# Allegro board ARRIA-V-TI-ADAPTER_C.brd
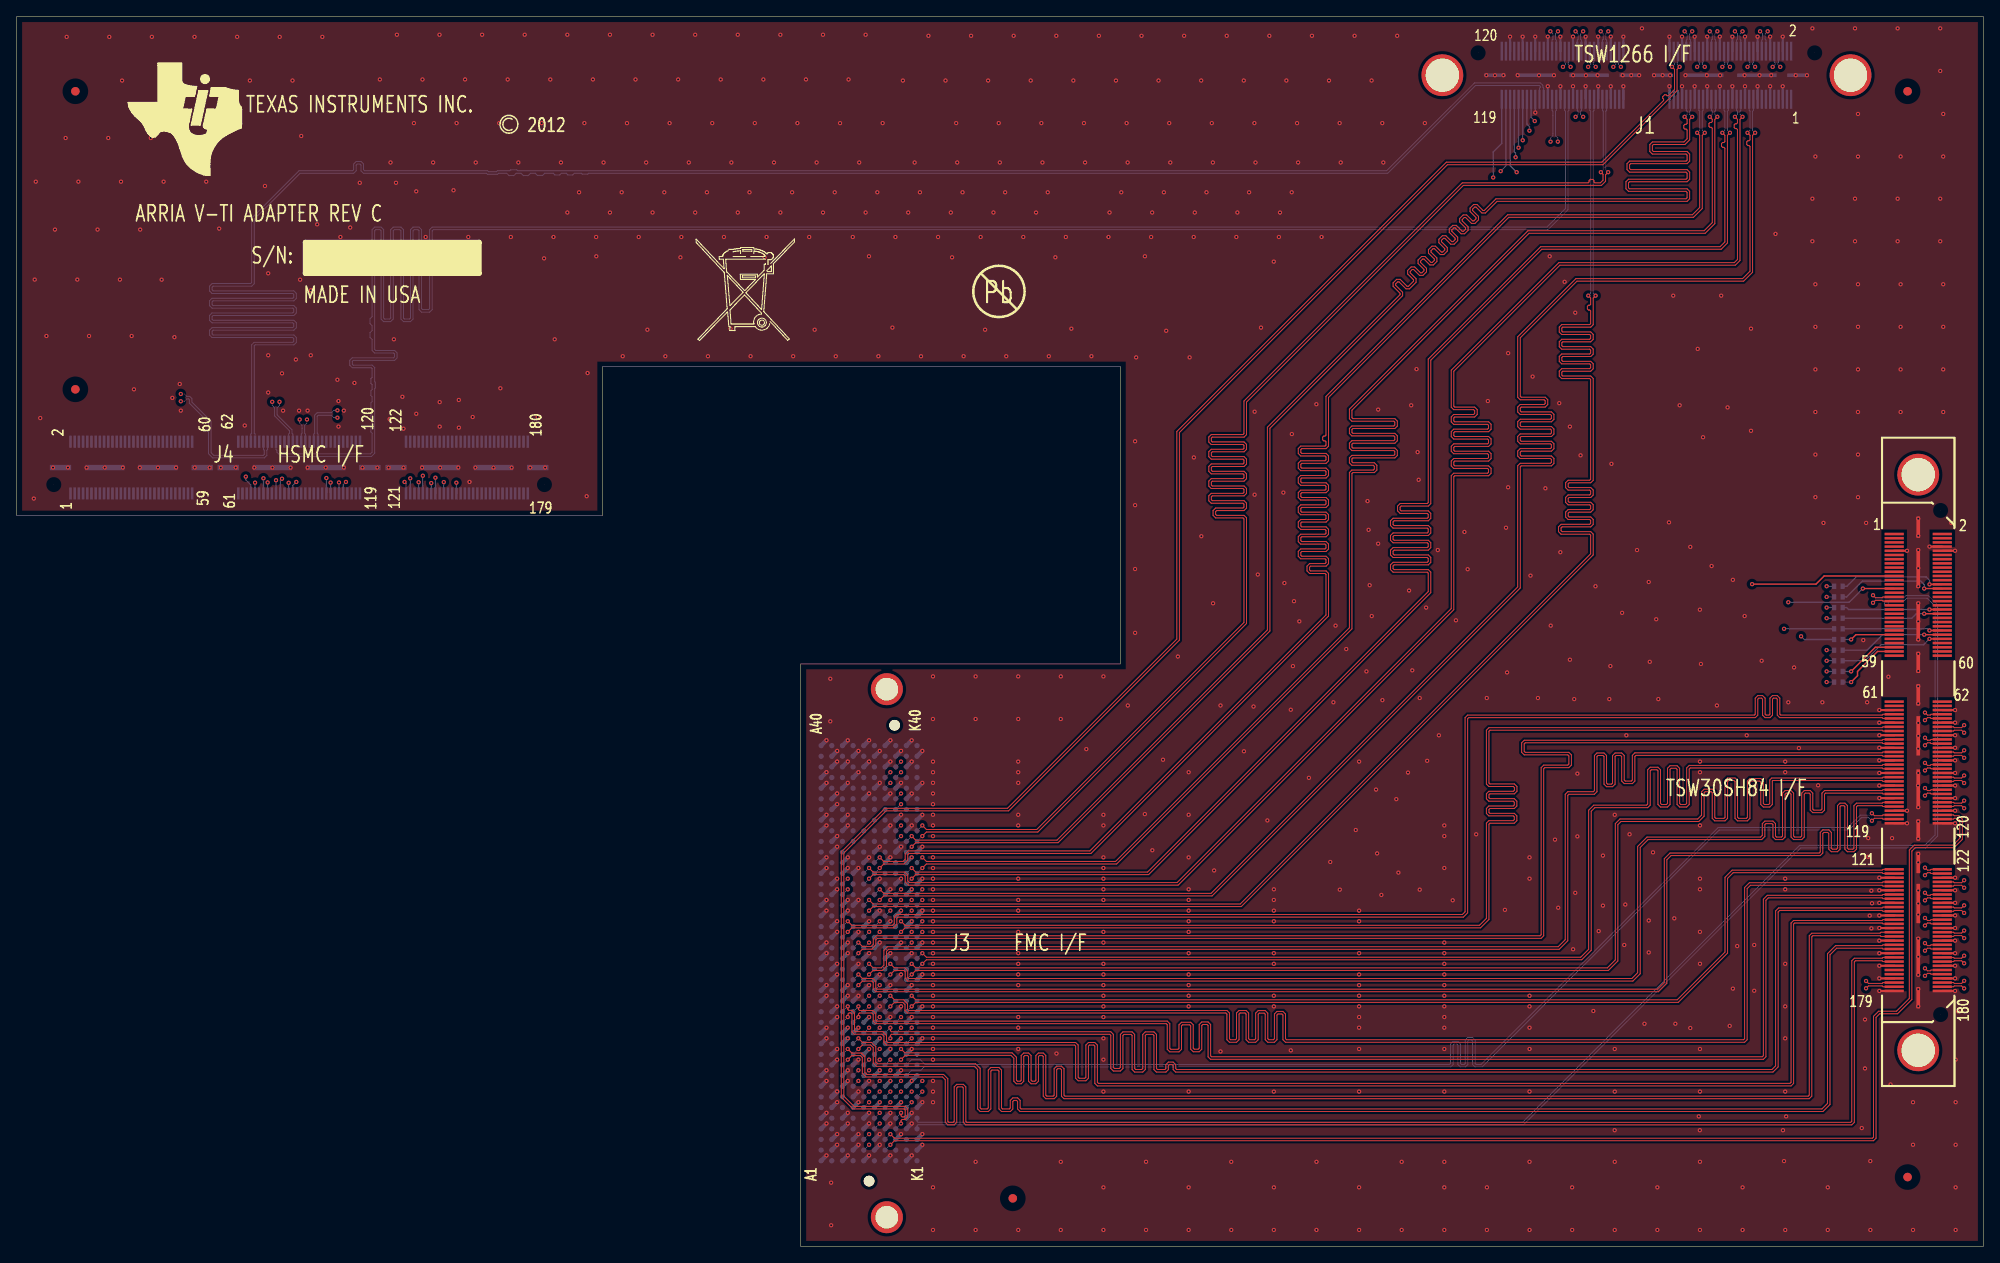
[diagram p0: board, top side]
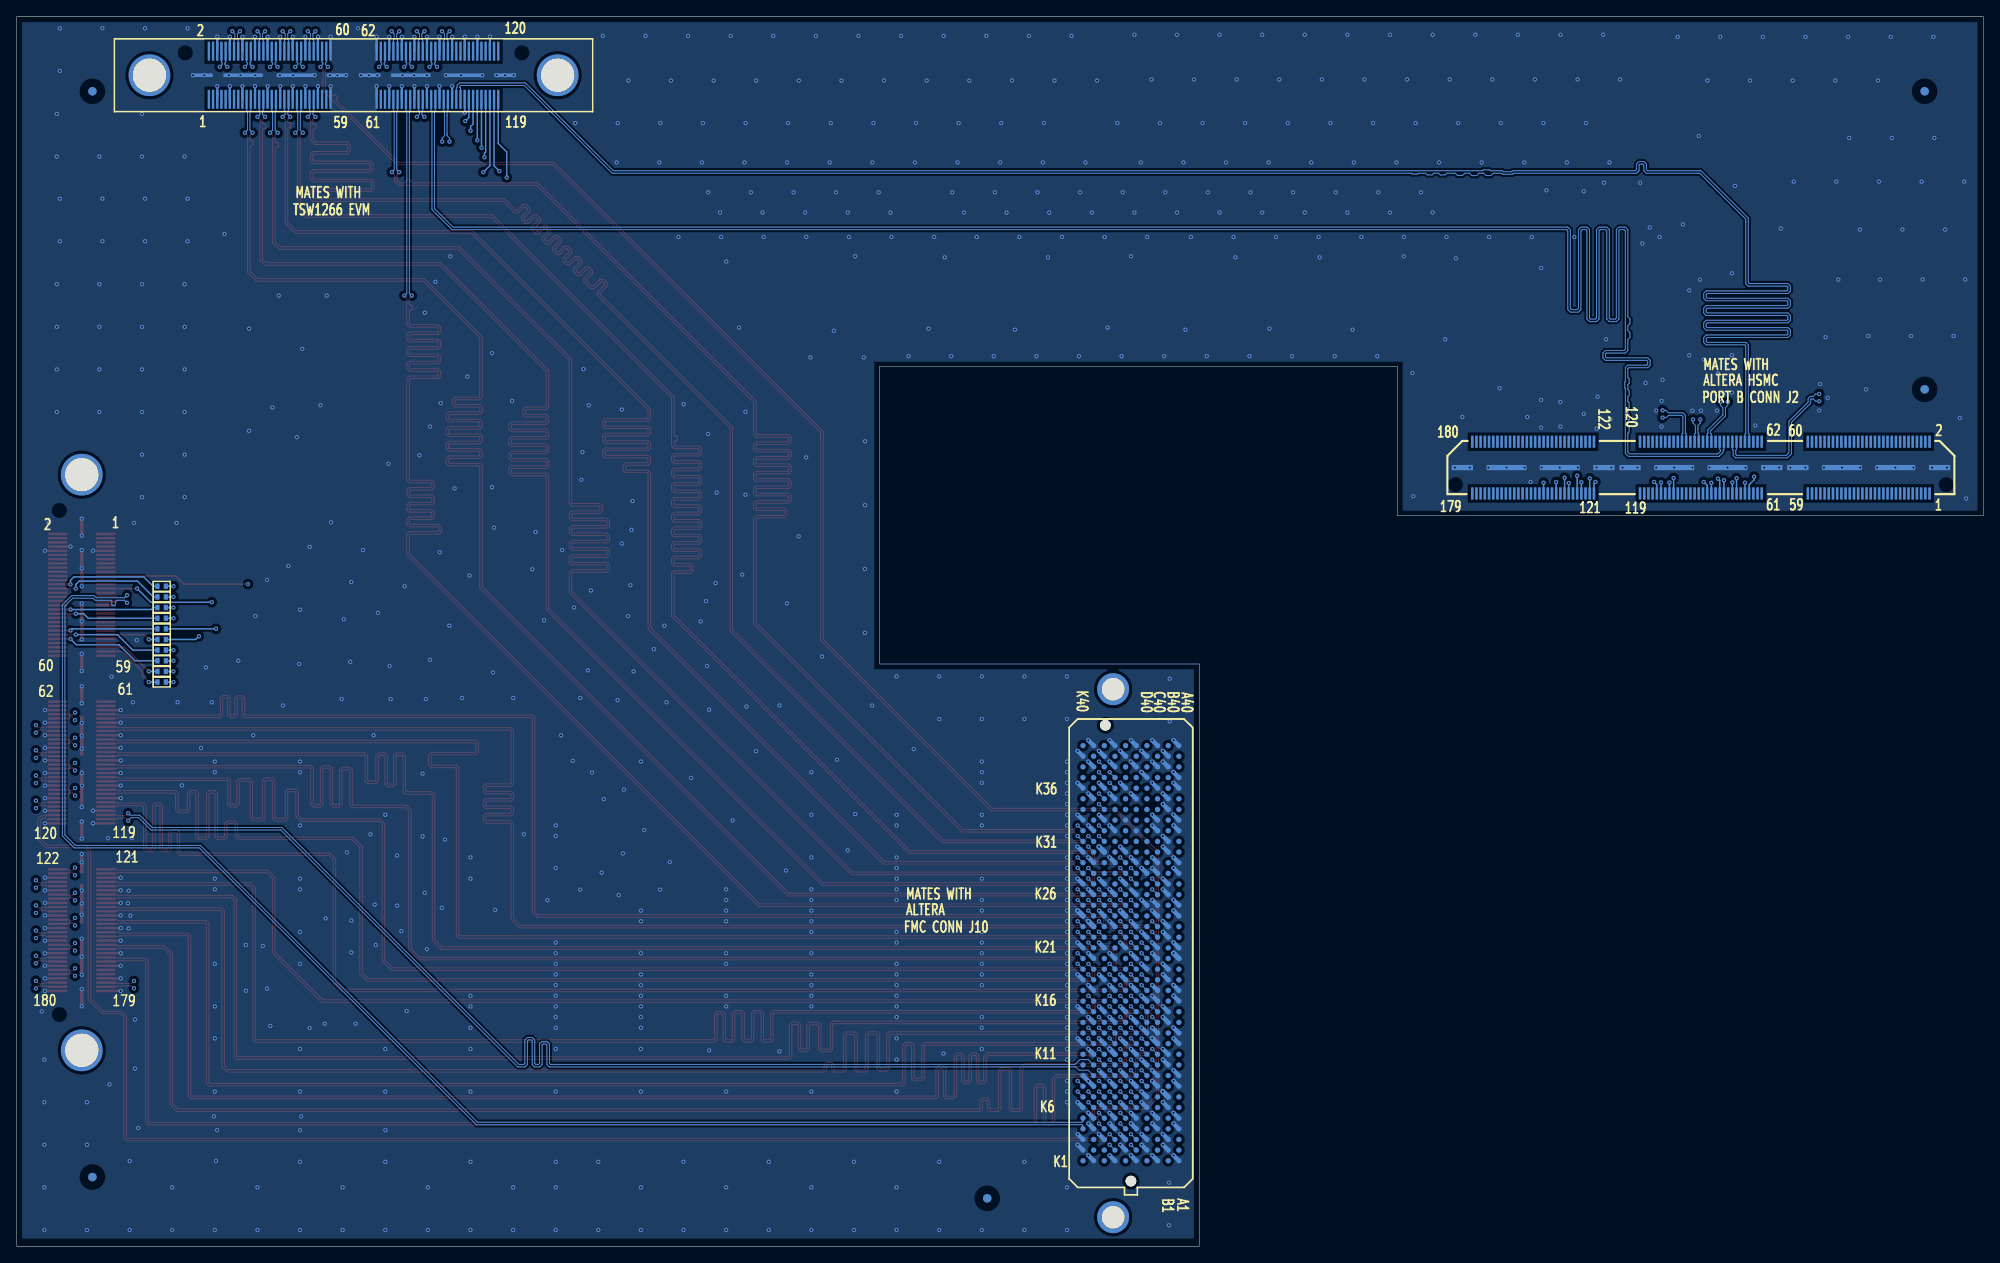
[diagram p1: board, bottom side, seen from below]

Outline 234.44 x 146.69 mm; copper layers: TOP, LAYER2_GND1, LAYER3, LAYER4_GND2, LAYER5_GND3, LAYER6, LAYER7_GND4, BOTTOM. Coordinates in mm from the lower left corner of the outline.
Outline path: 0,146.69 0,87.17 69.85,87.17 69.85,104.95 131.57,104.95 131.57,69.47 93.47,69.47 93.47,0 234.44,0 234.44,146.69 0,146.69

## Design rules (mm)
net group CDA0: nets DA0N DA0P
net group CDA10: nets DA10N DA10P
net group CDA11: nets DA11N DA11P
net group DDA1: nets DA1N DA1P
net group DDA2: nets DA2N DA2P
net group DDA3: nets DA3N DA3P
net group DDA4: nets DA4N DA4P
net group DDA5: nets DA5N DA5P
net group DDA6: nets DA6N DA6P
net group DDA7: nets DA7N DA7P
net group DDA8: nets DA8N DA8P
net group DDA9: nets DA9N DA9P
net group DDA12: nets DA12N DA12P
net group DDA13: nets DA13N DA13P
net group DDA14: nets DA14N DA14P
net group DDA15: nets DA15N DA15P
net group DDATACLK: nets DATACLKN DATACLKP
net group DDB0: nets DB0N DB0P
net group DDB1: nets DB1N DB1P
net group DDB2: nets DB2N DB2P
net group DDB3: nets DB3N DB3P
net group DDB4: nets DB4N DB4P
net group DDB5: nets DB5N DB5P
net group DDB6: nets DB6N DB6P
net group DDB7: nets DB7N DB7P
net group DDB8: nets DB8N DB8P
net group DDB9: nets DB9N DB9P
net group DDB10: nets DB10N DB10P
net group DDB11: nets DB11N DB11P
net group DDB12: nets DB12N DB12P
net group DDB13: nets DB13N DB13P
net group DDB14: nets DB14N DB14P
net group DDB15: nets DB15N DB15P
net group DIFFPAIR0: nets ADC_A0N ADC_A0P
net group DIFFPAIR1: nets ADC_A10N ADC_A10P
net group DIFFPAIR2: nets ADC_A11N ADC_A11P
net group DIFFPAIR3: nets ADC_A1N ADC_A1P
net group DIFFPAIR4: nets ADC_A2N ADC_A2P
net group DIFFPAIR5: nets ADC_A3N ADC_A3P
net group DIFFPAIR6: nets ADC_A4N ADC_A4P
net group DIFFPAIR7: nets ADC_A5N ADC_A5P
net group DIFFPAIR8: nets ADC_A6N ADC_A6P
net group DIFFPAIR9: nets ADC_A7N ADC_A7P
net group DIFFPAIR10: nets ADC_A8N ADC_A8P
net group DIFFPAIR11: nets ADC_A9N ADC_A9P
net group DIFFPAIR12: nets ADC_B0N ADC_B0P
net group DIFFPAIR13: nets ADC_B10N ADC_B10P
net group DIFFPAIR14: nets ADC_B11N ADC_B11P
net group DIFFPAIR15: nets ADC_B1N ADC_B1P
net group DIFFPAIR16: nets ADC_B2N ADC_B2P
net group DIFFPAIR17: nets ADC_B4N ADC_B4P
net group DIFFPAIR18: nets ADC_B3N ADC_B3P
net group DIFFPAIR19: nets ADC_B5N ADC_B5P
net group DIFFPAIR20: nets ADC_B6N ADC_B6P
net group DIFFPAIR21: nets ADC_B7N ADC_B7P
net group DIFFPAIR22: nets ADC_B8N ADC_B8P
net group DIFFPAIR23: nets FPGA_CLKOUTN2 FPGA_CLKOUTP2
net group DIFFPAIR24: nets FPGA_CLKOUTN1 FPGA_CLKOUTP1
net group DIFFPAIR25: nets ADC_B9N ADC_B9P
net group DIFFPAIR26: nets CLKOUTAN CLKOUTAP
net group DIFFPAIR27: nets ISTROBE_N ISTROBE_P
net group DIFFPAIR28: nets PARITY_N PARITY_P
net group DIFFPAIR29: nets SYNCA_N SYNCA_P
net group DIFFPAIR30: nets OVR_AN OVR_AP
net group OVRB: nets OVR_BN OVR_BP

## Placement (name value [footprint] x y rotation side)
J1  CON, SMVT, 120POS, HS GND PLANE, QSH  [CON_SMVT_120POS_QSH_SAMTEC_RT1]  194.29 139.71 180 bottom
J2  CON, SMVT, 180POS, HS GND PLANE, QSH  [CON_SMVT_180POS_QSH_SAMTEC_RT1]  229.36 87.82 270 top
J3  CON, SMVT, 40X10, ASP  [CON_SMVT_40X10_ASP-134487-01]  101.61 34.96 270 bottom
J4  CON, SMVT, 180POS, HS GND PLANE, ASP-QTH  [CON_SMVT_180POS_QTH_SAMTEC]  33.66 92.9 0 bottom
NOREF  -  []  93.47 0 90 top
NOREF#2  -  []  0 87.17 90 top
NOREF#3  -  []  180.72 171.45 0 top
NOREF#4  -  []  -124.46 -158.75 0 top
NOREF#5  -  []  0 146.69 0 top
NOREF#6  -  []  255.4 178.94 0 top
NOREF#7  -  []  131.57 69.47 90 top
NOREF#8  -  []  668.02 176.78 0 top
NOREF#9  -  []  234.44 0 90 top
NOREF#10  -  [unnamed#2]  225.43 137.79 0 top
NOREF#11  -  []  124.97 200.28 0 top
NOREF#12  -  []  209.55 48.26 0 top
NOREF#13  -  []  268.61 177.29 0 top
NOREF#14  -  []  -110.49 320.68 0 top
NOREF#15  -  []  93.47 0 0 top
NOREF#16  -  []  57.68 143.92 0 top
NOREF#17  -  []  223.29 96.44 0 top
NOREF#18  -  []  0 87.17 90 top
NOREF#19  -  []  189.94 170.1 0 top
NOREF#20  -  []  240.31 178.44 0 top
NOREF#21  -  [unnamed#2]  6.98 137.79 0 top
NOREF#22  -  []  93.47 0 0 top
NOREF#23  -  [unnamed#2]  6.98 102.23 0 top
NOREF#24  -  []  69.85 104.95 0 top
NOREF#25  -  [unnamed#2]  118.74 5.71 0 top
NOREF#26  -  []  93.47 31.59 0 top
NOREF#27  -  []  13.68 88.69 0 top
NOREF#28  -  [unnamed#2]  225.43 8.26 0 top
NOREF#29  -  []  93.47 0 90 top
NOREF#30  -  [unnamed#2]  225.43 8.26 180 bottom
NOREF#31  -  [unnamed#2]  6.98 137.79 180 bottom
NOREF#32  -  [unnamed#2]  103.73 3.46 180 bottom
NOREF#33  -  [unnamed#2]  6.98 102.23 180 bottom
NOREF#34  -  [unnamed#2]  225.43 137.79 180 bottom
NOREF#35  -  [unnamed#2]  103.73 66.46 180 bottom
NOREF#36  -  [unnamed#2]  118.74 5.71 180 bottom
R1  0  [0402]  217.17 78.74 0 bottom
R2  0  [0402]  217.17 77.47 0 bottom
R3  0  [0402]  217.17 76.2 0 bottom
R4  0  [0402]  217.17 74.93 0 bottom
R5  0  [0402]  217.17 73.66 0 bottom
R7  0  [0402]  217.17 71.12 0 bottom
R8  0  [0402]  217.17 72.39 180 bottom
R9  0  [0402]  217.17 69.85 0 bottom
R12  0  [0402]  217.17 68.58 180 bottom
R14  0  [0402]  217.17 67.31 180 bottom

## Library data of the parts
J1 = CON_SMVT_120POS_QSH_SAMTEC
J2 = CON_SMVT_180POS_QSH_SAMTEC
J3 = CON_SMVT_40X10_ASP-134487-01
J4 = CON_SMVT_180POS_QTH_SAMTEC
R1-R5 R7-R9 R12 R14 = R_5

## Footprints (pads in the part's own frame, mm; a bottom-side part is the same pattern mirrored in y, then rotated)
0402
  rect 0.508x0.635 smd: 1(-0.508,0) 2(0.508,0)
CON_SMVT_40X10_ASP-134487-01
  round 1.27 hole 1.27 unplated: (-27.191,-3.048) (27.191,0)
  round 0.635 smd: A1(24.765,5.715) A2(23.495,5.715) A3(22.225,5.715) A4(20.955,5.715) A5(19.685,5.715) A6(18.415,5.715) A7(17.145,5.715) A8(15.875,5.715) A9(14.605,5.715) A10(13.335,5.715) A11(12.065,5.715) A12(10.795,5.715) A13(9.525,5.715) A14(8.255,5.715) A15(6.985,5.715) A16(5.715,5.715) A17(4.445,5.715) A18(3.175,5.715) A19(1.905,5.715) A20(0.635,5.715) A21(-0.635,5.715) A22(-1.905,5.715) A23(-3.175,5.715) A24(-4.445,5.715) A25(-5.715,5.715) A26(-6.985,5.715) A27(-8.255,5.715) A28(-9.525,5.715) A29(-10.795,5.715) A30(-12.065,5.715) A31(-13.335,5.715) A32(-14.605,5.715) A33(-15.875,5.715) A34(-17.145,5.715) A35(-18.415,5.715) A36(-19.685,5.715) A37(-20.955,5.715) A38(-22.225,5.715) A39(-23.495,5.715) A40(-24.765,5.715) B1(24.765,4.445) B2(23.495,4.445) B3(22.225,4.445) B4(20.955,4.445) B5(19.685,4.445) B6(18.415,4.445) B7(17.145,4.445) B8(15.875,4.445) B9(14.605,4.445) B10(13.335,4.445) B11(12.065,4.445) B12(10.795,4.445) B13(9.525,4.445) B14(8.255,4.445) B15(6.985,4.445) B16(5.715,4.445) B17(4.445,4.445) B18(3.175,4.445) B19(1.905,4.445) B20(0.635,4.445) B21(-0.635,4.445) B22(-1.905,4.445) B23(-3.175,4.445) B24(-4.445,4.445) B25(-5.715,4.445) B26(-6.985,4.445) B27(-8.255,4.445) B28(-9.525,4.445) B29(-10.795,4.445) B30(-12.065,4.445) B31(-13.335,4.445) B32(-14.605,4.445) B33(-15.875,4.445) B34(-17.145,4.445) B35(-18.415,4.445) B36(-19.685,4.445) B37(-20.955,4.445) B38(-22.225,4.445) B39(-23.495,4.445) B40(-24.765,4.445) C1(24.765,3.175) C2(23.495,3.175) C3(22.225,3.175) C4(20.955,3.175) C5(19.685,3.175) C6(18.415,3.175) C7(17.145,3.175) C8(15.875,3.175) C9(14.605,3.175) C10(13.335,3.175) C11(12.065,3.175) C12(10.795,3.175) C13(9.525,3.175) C14(8.255,3.175) C15(6.985,3.175) C16(5.715,3.175) C17(4.445,3.175) C18(3.175,3.175) C19(1.905,3.175) C20(0.635,3.175) C21(-0.635,3.175) C22(-1.905,3.175) C23(-3.175,3.175) C24(-4.445,3.175) C25(-5.715,3.175) C26(-6.985,3.175) C27(-8.255,3.175) C28(-9.525,3.175) C29(-10.795,3.175) C30(-12.065,3.175) C31(-13.335,3.175) C32(-14.605,3.175) C33(-15.875,3.175) C34(-17.145,3.175) C35(-18.415,3.175) C36(-19.685,3.175) C37(-20.955,3.175) C38(-22.225,3.175) C39(-23.495,3.175) C40(-24.765,3.175) D1(24.765,1.905) D2(23.495,1.905) D3(22.225,1.905) D4(20.955,1.905) D5(19.685,1.905) D6(18.415,1.905) D7(17.145,1.905) D8(15.875,1.905) D9(14.605,1.905) D10(13.335,1.905) D11(12.065,1.905) D12(10.795,1.905) D13(9.525,1.905) D14(8.255,1.905) D15(6.985,1.905) D16(5.715,1.905) D17(4.445,1.905) D18(3.175,1.905) D19(1.905,1.905) D20(0.635,1.905) D21(-0.635,1.905) D22(-1.905,1.905) D23(-3.175,1.905) D24(-4.445,1.905) D25(-5.715,1.905) D26(-6.985,1.905) D27(-8.255,1.905) D28(-9.525,1.905) D29(-10.795,1.905) D30(-12.065,1.905) D31(-13.335,1.905) D32(-14.605,1.905) D33(-15.875,1.905) D34(-17.145,1.905) D35(-18.415,1.905) D36(-19.685,1.905) D37(-20.955,1.905) D38(-22.225,1.905) D39(-23.495,1.905) D40(-24.765,1.905) E1(24.765,0.635) E2(23.495,0.635) E3(22.225,0.635) E4(20.955,0.635) E5(19.685,0.635) E6(18.415,0.635) E7(17.145,0.635) E8(15.875,0.635) E9(14.605,0.635) E10(13.335,0.635) E11(12.065,0.635) E12(10.795,0.635) E13(9.525,0.635) E14(8.255,0.635) E15(6.985,0.635) E16(5.715,0.635) E17(4.445,0.635) E18(3.175,0.635) E19(1.905,0.635) E20(0.635,0.635) E21(-0.635,0.635) E22(-1.905,0.635) E23(-3.175,0.635) E24(-4.445,0.635) E25(-5.715,0.635) E26(-6.985,0.635) E27(-8.255,0.635) E28(-9.525,0.635) E29(-10.795,0.635) E30(-12.065,0.635) E31(-13.335,0.635) E32(-14.605,0.635) E33(-15.875,0.635) E34(-17.145,0.635) E35(-18.415,0.635) E36(-19.685,0.635) E37(-20.955,0.635) E38(-22.225,0.635) E39(-23.495,0.635) E40(-24.765,0.635) F1(24.765,-0.635) F2(23.495,-0.635) F3(22.225,-0.635) F4(20.955,-0.635) F5(19.685,-0.635) F6(18.415,-0.635) F7(17.145,-0.635) F8(15.875,-0.635) F9(14.605,-0.635) F10(13.335,-0.635) F11(12.065,-0.635) F12(10.795,-0.635) F13(9.525,-0.635) F14(8.255,-0.635) F15(6.985,-0.635) F16(5.715,-0.635) F17(4.445,-0.635) F18(3.175,-0.635) F19(1.905,-0.635) F20(0.635,-0.635) F21(-0.635,-0.635) F22(-1.905,-0.635) F23(-3.175,-0.635) F24(-4.445,-0.635) F25(-5.715,-0.635) F26(-6.985,-0.635) F27(-8.255,-0.635) F28(-9.525,-0.635) F29(-10.795,-0.635) F30(-12.065,-0.635) F31(-13.335,-0.635) F32(-14.605,-0.635) F33(-15.875,-0.635) F34(-17.145,-0.635) F35(-18.415,-0.635) F36(-19.685,-0.635) F37(-20.955,-0.635) F38(-22.225,-0.635) F39(-23.495,-0.635) F40(-24.765,-0.635) G1(24.765,-1.905) G2(23.495,-1.905) G3(22.225,-1.905) G4(20.955,-1.905) G5(19.685,-1.905) G6(18.415,-1.905) G7(17.145,-1.905) G8(15.875,-1.905) G9(14.605,-1.905) G10(13.335,-1.905) G11(12.065,-1.905) G12(10.795,-1.905) G13(9.525,-1.905) G14(8.255,-1.905) G15(6.985,-1.905) G16(5.715,-1.905) G17(4.445,-1.905) G18(3.175,-1.905) G19(1.905,-1.905) G20(0.635,-1.905) G21(-0.635,-1.905) G22(-1.905,-1.905) G23(-3.175,-1.905) G24(-4.445,-1.905) G25(-5.715,-1.905) G26(-6.985,-1.905) G27(-8.255,-1.905) G28(-9.525,-1.905) G29(-10.795,-1.905) G30(-12.065,-1.905) G31(-13.335,-1.905) G32(-14.605,-1.905) G33(-15.875,-1.905) G34(-17.145,-1.905) G35(-18.415,-1.905) G36(-19.685,-1.905) G37(-20.955,-1.905) G38(-22.225,-1.905) G39(-23.495,-1.905) G40(-24.765,-1.905) H1(24.765,-3.175) H2(23.495,-3.175) H3(22.225,-3.175) H4(20.955,-3.175) H5(19.685,-3.175) H6(18.415,-3.175) H7(17.145,-3.175) H8(15.875,-3.175) H9(14.605,-3.175) H10(13.335,-3.175) H11(12.065,-3.175) H12(10.795,-3.175) H13(9.525,-3.175) H14(8.255,-3.175) H15(6.985,-3.175) H16(5.715,-3.175) H17(4.445,-3.175) H18(3.175,-3.175) H19(1.905,-3.175) H20(0.635,-3.175) H21(-0.635,-3.175) H22(-1.905,-3.175) H23(-3.175,-3.175) H24(-4.445,-3.175) H25(-5.715,-3.175) H26(-6.985,-3.175) H27(-8.255,-3.175) H28(-9.525,-3.175) H29(-10.795,-3.175) H30(-12.065,-3.175) H31(-13.335,-3.175) H32(-14.605,-3.175) H33(-15.875,-3.175) H34(-17.145,-3.175) H35(-18.415,-3.175) H36(-19.685,-3.175) H37(-20.955,-3.175) H38(-22.225,-3.175) H39(-23.495,-3.175) H40(-24.765,-3.175) J1(24.765,-4.445) J2(23.495,-4.445) J3(22.225,-4.445) J4(20.955,-4.445) J5(19.685,-4.445) J6(18.415,-4.445) J7(17.145,-4.445) J8(15.875,-4.445) J9(14.605,-4.445) J10(13.335,-4.445) J11(12.065,-4.445) J12(10.795,-4.445) J13(9.525,-4.445) J14(8.255,-4.445) J15(6.985,-4.445) J16(5.715,-4.445) J17(4.445,-4.445) J18(3.175,-4.445) J19(1.905,-4.445) J20(0.635,-4.445) J21(-0.635,-4.445) J22(-1.905,-4.445) J23(-3.175,-4.445) J24(-4.445,-4.445) J25(-5.715,-4.445) J26(-6.985,-4.445) J27(-8.255,-4.445) J28(-9.525,-4.445) J29(-10.795,-4.445) J30(-12.065,-4.445) J31(-13.335,-4.445) J32(-14.605,-4.445) J33(-15.875,-4.445) J34(-17.145,-4.445) J35(-18.415,-4.445) J36(-19.685,-4.445) J37(-20.955,-4.445) J38(-22.225,-4.445) J39(-23.495,-4.445) J40(-24.765,-4.445) K1(24.765,-5.715) K2(23.495,-5.715) K3(22.225,-5.715) K4(20.955,-5.715) K5(19.685,-5.715) K6(18.415,-5.715) K7(17.145,-5.715) K8(15.875,-5.715) K9(14.605,-5.715) K10(13.335,-5.715) K11(12.065,-5.715) K12(10.795,-5.715) K13(9.525,-5.715) K14(8.255,-5.715) K15(6.985,-5.715) K16(5.715,-5.715) K17(4.445,-5.715) K18(3.175,-5.715) K19(1.905,-5.715) K20(0.635,-5.715) K21(-0.635,-5.715) K22(-1.905,-5.715) K23(-3.175,-5.715) K24(-4.445,-5.715) K25(-5.715,-5.715) K26(-6.985,-5.715) K27(-8.255,-5.715) K28(-9.525,-5.715) K29(-10.795,-5.715) K30(-12.065,-5.715) K31(-13.335,-5.715) K32(-14.605,-5.715) K33(-15.875,-5.715) K34(-17.145,-5.715) K35(-18.415,-5.715) K36(-19.685,-5.715) K37(-20.955,-5.715) K38(-22.225,-5.715) K39(-23.495,-5.715) K40(-24.765,-5.715)
CON_SMVT_120POS_QSH_SAMTEC_RT1
  round 4.978 hole 3.962: (-24.332,0) (24.332,0)
  round 0.025 hole 1.016 unplated: (-20.06,2.67) (20.07,2.67)
  rect 0.279x2.261 smd: 1(-17.25,-2.87) 2(-17.25,2.87) 3(-16.75,-2.87) 4(-16.75,2.87) 5(-16.25,-2.87) 6(-16.25,2.87) 7(-15.75,-2.87) 8(-15.75,2.87) 9(-15.25,-2.87) 10(-15.25,2.87) 11(-14.75,-2.87) 12(-14.75,2.87) 13(-14.25,-2.87) 14(-14.25,2.87) 15(-13.75,-2.87) 16(-13.75,2.87) 17(-13.25,-2.87) 18(-13.25,2.87) 19(-12.75,-2.87) 20(-12.75,2.87) 21(-12.25,-2.87) 22(-12.25,2.87) 23(-11.75,-2.87) 24(-11.75,2.87) 25(-11.25,-2.87) 26(-11.25,2.87) 27(-10.75,-2.87) 28(-10.75,2.87) 29(-10.25,-2.87) 30(-10.25,2.87) 31(-9.75,-2.87) 32(-9.75,2.87) 33(-9.25,-2.87) 34(-9.25,2.87) 35(-8.75,-2.87) 36(-8.75,2.87) 37(-8.25,-2.87) 38(-8.25,2.87) 39(-7.75,-2.87) 40(-7.75,2.87) 41(-7.25,-2.87) 42(-7.25,2.87) 43(-6.75,-2.87) 44(-6.75,2.87) 45(-6.25,-2.87) 46(-6.25,2.87) 47(-5.75,-2.87) 48(-5.75,2.87) 49(-5.25,-2.87) 50(-5.25,2.87) 51(-4.75,-2.87) 52(-4.75,2.87) 53(-4.25,-2.87) 54(-4.25,2.87) 55(-3.75,-2.87) 56(-3.75,2.87) 57(-3.25,-2.87) 58(-3.25,2.87) 59(-2.75,-2.87) 60(-2.75,2.87) 61(2.75,-2.87) 62(2.75,2.87) 63(3.25,-2.87) 64(3.25,2.87) 65(3.75,-2.87) 66(3.75,2.87) 67(4.25,-2.87) 68(4.25,2.87) 69(4.75,-2.87) 70(4.75,2.87) 71(5.25,-2.87) 72(5.25,2.87) 73(5.75,-2.87) 74(5.75,2.87) 75(6.25,-2.87) 76(6.25,2.87) 77(6.75,-2.87) 78(6.75,2.87) 79(7.25,-2.87) 80(7.25,2.87) 81(7.75,-2.87) 82(7.75,2.87) 83(8.25,-2.87) 84(8.25,2.87) 85(8.75,-2.87) 86(8.75,2.87) 87(9.25,-2.87) 88(9.25,2.87) 89(9.75,-2.87) 90(9.75,2.87) 91(10.25,-2.87) 92(10.25,2.87) 93(10.75,-2.87) 94(10.75,2.87) 95(11.25,-2.87) 96(11.25,2.87) 97(11.75,-2.87) 98(11.75,2.87) 99(12.25,-2.87) 100(12.25,2.87) 101(12.75,-2.87) 102(12.75,2.87) 103(13.25,-2.87) 104(13.25,2.87) 105(13.75,-2.87) 106(13.75,2.87) 107(14.25,-2.87) 108(14.25,2.87) 109(14.75,-2.87) 110(14.75,2.87) 111(15.25,-2.87) 112(15.25,2.87) 113(15.75,-2.87) 114(15.75,2.87) 115(16.25,-2.87) 116(16.25,2.87) 117(16.75,-2.87) 118(16.75,2.87) 119(17.25,-2.87) 120(17.25,2.87)
  rect 2.54x0.432 smd: 121(-18.06,0) 124(-1.93,0) 125(1.94,0) 128(18.07,0)
  rect 4.699x0.432 smd: 122(-13.17,0) 123(-6.82,0) 126(6.83,0) 127(13.18,0)
CON_SMVT_180POS_QSH_SAMTEC_RT1
  round 4.978 hole 3.962: (-4.234,-2.667) (64.447,-2.667)
  round 0.025 hole 1.016 unplated: (0.036,0) (60.175,0)
  rect 0.305x2.286 smd: 1(2.847,-5.532) 2(2.847,0.198) 3(3.348,-5.532) 4(3.348,0.198) 5(3.848,-5.532) 6(3.848,0.198) 7(4.348,-5.532) 8(4.348,0.198) 9(4.849,-5.532) 10(4.849,0.198) 11(5.349,-5.532) 12(5.349,0.198) 13(5.85,-5.532) 14(5.85,0.198) 15(6.35,-5.532) 16(6.35,0.198) 17(6.85,-5.532) 18(6.85,0.198) 19(7.351,-5.532) 20(7.351,0.198) 21(7.851,-5.532) 22(7.851,0.198) 23(8.352,-5.532) 24(8.352,0.198) 25(8.852,-5.532) 26(8.852,0.198) 27(9.352,-5.532) 28(9.352,0.198) 29(9.853,-5.532) 30(9.853,0.198) 31(10.353,-5.532) 32(10.353,0.198) 33(10.853,-5.532) 34(10.853,0.198) 35(11.354,-5.532) 36(11.354,0.198) 37(11.854,-5.532) 38(11.854,0.198) 39(12.355,-5.532) 40(12.355,0.198) 41(12.855,-5.532) 42(12.855,0.198) 43(13.355,-5.532) 44(13.355,0.198) 45(13.856,-5.532) 46(13.856,0.198) 47(14.356,-5.532) 48(14.356,0.198) 49(14.856,-5.532) 50(14.856,0.198) 51(15.357,-5.532) 52(15.357,0.198) 53(15.857,-5.532) 54(15.857,0.198) 55(16.358,-5.532) 56(16.358,0.198) 57(16.858,-5.532) 58(16.858,0.198) 59(17.358,-5.532) 60(17.358,0.198) 61(22.85,-5.532) 62(22.85,0.198) 63(23.35,-5.532) 64(23.35,0.198) 65(23.851,-5.532) 66(23.851,0.198) 67(24.351,-5.532) 68(24.351,0.198) 69(24.851,-5.532) 70(24.851,0.198) 71(25.352,-5.532) 72(25.352,0.198) 73(25.852,-5.532) 74(25.852,0.198) 75(26.352,-5.532) 76(26.352,0.198) 77(26.853,-5.532) 78(26.853,0.198) 79(27.353,-5.532) 80(27.353,0.198) 81(27.854,-5.532) 82(27.854,0.198) 83(28.354,-5.532) 84(28.354,0.198) 85(28.854,-5.532) 86(28.854,0.198) 87(29.355,-5.532) 88(29.355,0.198) 89(29.855,-5.532) 90(29.855,0.198) 91(30.356,-5.532) 92(30.356,0.198) 93(30.856,-5.532) 94(30.856,0.198) 95(31.356,-5.532) 96(31.356,0.198) 97(31.857,-5.532) 98(31.857,0.198) 99(32.357,-5.532) 100(32.357,0.198) 101(32.857,-5.532) 102(32.857,0.198) 103(33.358,-5.532) 104(33.358,0.198) 105(33.858,-5.532) 106(33.858,0.198) 107(34.359,-5.532) 108(34.359,0.198) 109(34.859,-5.532) 110(34.859,0.198) 111(35.359,-5.532) 112(35.359,0.198) 113(35.86,-5.532) 114(35.86,0.198) 115(36.36,-5.532) 116(36.36,0.198) 117(36.86,-5.532) 118(36.86,0.198) 119(37.361,-5.532) 120(37.361,0.198) 121(42.852,-5.532) 122(42.852,0.198) 123(43.353,-5.532) 124(43.353,0.198) 125(43.853,-5.532) 126(43.853,0.198) 127(44.353,-5.532) 128(44.353,0.198) 129(44.854,-5.532) 130(44.854,0.198) 131(45.354,-5.532) 132(45.354,0.198) 133(45.855,-5.532) 134(45.855,0.198) 135(46.355,-5.532) 136(46.355,0.198) 137(46.855,-5.532) 138(46.855,0.198) 139(47.356,-5.532) 140(47.356,0.198) 141(47.856,-5.532) 142(47.856,0.198) 143(48.357,-5.532) 144(48.357,0.198) 145(48.857,-5.532) 146(48.857,0.198) 147(49.357,-5.532) 148(49.357,0.198) 149(49.858,-5.532) 150(49.858,0.198) 151(50.358,-5.532) 152(50.358,0.198) 153(50.858,-5.532) 154(50.858,0.198) 155(51.359,-5.532) 156(51.359,0.198) 157(51.859,-5.532) 158(51.859,0.198) 159(52.36,-5.532) 160(52.36,0.198) 161(52.86,-5.532) 162(52.86,0.198) 163(53.36,-5.532) 164(53.36,0.198) 165(53.861,-5.532) 166(53.861,0.198) 167(54.361,-5.532) 168(54.361,0.198) 169(54.861,-5.532) 170(54.861,0.198) 171(55.362,-5.532) 172(55.362,0.198) 173(55.862,-5.532) 174(55.862,0.198) 175(56.363,-5.532) 176(56.363,0.198) 177(56.863,-5.532) 178(56.863,0.198) 179(57.363,-5.532) 180(57.363,0.198)
  rect 2.54x0.432 smd: 181(2.035,-2.667) 184(18.164,-2.667) 185(22.037,-2.667) 188(38.166,-2.667) 189(42.04,-2.667) 192(58.169,-2.667)
  rect 4.699x0.432 smd: 182(6.924,-2.667) 183(13.274,-2.667) 186(26.927,-2.667) 187(33.277,-2.667) 190(46.929,-2.667) 191(53.279,-2.667)
CON_SMVT_180POS_QTH_SAMTEC
  round 0.025 hole 1.016 unplated: (-29.247,2.032) (29.249,2.032)
  rect 0.305x1.448 smd: 1(-27.258,3.086) 2(-27.258,-3.086) 3(-26.758,3.086) 4(-26.758,-3.086) 5(-26.257,3.086) 6(-26.257,-3.086) 7(-25.757,3.086) 8(-25.757,-3.086) 9(-25.256,3.086) 10(-25.256,-3.086) 11(-24.756,3.086) 12(-24.756,-3.086) 13(-24.256,3.086) 14(-24.256,-3.086) 15(-23.755,3.086) 16(-23.755,-3.086) 17(-23.255,3.086) 18(-23.255,-3.086) 19(-22.755,3.086) 20(-22.755,-3.086) 21(-22.254,3.086) 22(-22.254,-3.086) 23(-21.754,3.086) 24(-21.754,-3.086) 25(-21.253,3.086) 26(-21.253,-3.086) 27(-20.753,3.086) 28(-20.753,-3.086) 29(-20.253,3.086) 30(-20.253,-3.086) 31(-19.752,3.086) 32(-19.752,-3.086) 33(-19.252,3.086) 34(-19.252,-3.086) 35(-18.752,3.086) 36(-18.752,-3.086) 37(-18.251,3.086) 38(-18.251,-3.086) 39(-17.751,3.086) 40(-17.751,-3.086) 41(-17.25,3.086) 42(-17.25,-3.086) 43(-16.75,3.086) 44(-16.75,-3.086) 45(-16.25,3.086) 46(-16.25,-3.086) 47(-15.749,3.086) 48(-15.749,-3.086) 49(-15.249,3.086) 50(-15.249,-3.086) 51(-14.749,3.086) 52(-14.749,-3.086) 53(-14.248,3.086) 54(-14.248,-3.086) 55(-13.748,3.086) 56(-13.748,-3.086) 57(-13.247,3.086) 58(-13.247,-3.086) 59(-12.747,3.086) 60(-12.747,-3.086) 61(-7.256,3.086) 62(-7.256,-3.086) 63(-6.755,3.086) 64(-6.755,-3.086) 65(-6.255,3.086) 66(-6.255,-3.086) 67(-5.754,3.086) 68(-5.754,-3.086) 69(-5.254,3.086) 70(-5.254,-3.086) 71(-4.754,3.086) 72(-4.754,-3.086) 73(-4.253,3.086) 74(-4.253,-3.086) 75(-3.753,3.086) 76(-3.753,-3.086) 77(-3.252,3.086) 78(-3.252,-3.086) 79(-2.752,3.086) 80(-2.752,-3.086) 81(-2.252,3.086) 82(-2.252,-3.086) 83(-1.751,3.086) 84(-1.751,-3.086) 85(-1.251,3.086) 86(-1.251,-3.086) 87(-0.751,3.086) 88(-0.751,-3.086) 89(-0.25,3.086) 90(-0.25,-3.086) 91(0.25,3.086) 92(0.25,-3.086) 93(0.751,3.086) 94(0.751,-3.086) 95(1.251,3.086) 96(1.251,-3.086) 97(1.751,3.086) 98(1.751,-3.086) 99(2.252,3.086) 100(2.252,-3.086) 101(2.752,3.086) 102(2.752,-3.086) 103(3.252,3.086) 104(3.252,-3.086) 105(3.753,3.086) 106(3.753,-3.086) 107(4.253,3.086) 108(4.253,-3.086) 109(4.754,3.086) 110(4.754,-3.086) 111(5.254,3.086) 112(5.254,-3.086) 113(5.754,3.086) 114(5.754,-3.086) 115(6.255,3.086) 116(6.255,-3.086) 117(6.755,3.086) 118(6.755,-3.086) 119(7.256,3.086) 120(7.256,-3.086) 121(12.747,3.086) 122(12.747,-3.086) 123(13.247,3.086) 124(13.247,-3.086) 125(13.748,3.086) 126(13.748,-3.086) 127(14.248,3.086) 128(14.248,-3.086) 129(14.749,3.086) 130(14.749,-3.086) 131(15.249,3.086) 132(15.249,-3.086) 133(15.749,3.086) 134(15.749,-3.086) 135(16.25,3.086) 136(16.25,-3.086) 137(16.75,3.086) 138(16.75,-3.086) 139(17.25,3.086) 140(17.25,-3.086) 141(17.751,3.086) 142(17.751,-3.086) 143(18.251,3.086) 144(18.251,-3.086) 145(18.752,3.086) 146(18.752,-3.086) 147(19.252,3.086) 148(19.252,-3.086) 149(19.752,3.086) 150(19.752,-3.086) 151(20.253,3.086) 152(20.253,-3.086) 153(20.753,3.086) 154(20.753,-3.086) 155(21.253,3.086) 156(21.253,-3.086) 157(21.754,3.086) 158(21.754,-3.086) 159(22.254,3.086) 160(22.254,-3.086) 161(22.755,3.086) 162(22.755,-3.086) 163(23.255,3.086) 164(23.255,-3.086) 165(23.755,3.086) 166(23.755,-3.086) 167(24.256,3.086) 168(24.256,-3.086) 169(24.756,3.086) 170(24.756,-3.086) 171(25.256,3.086) 172(25.256,-3.086) 173(25.757,3.086) 174(25.757,-3.086) 175(26.257,3.086) 176(26.257,-3.086) 177(26.758,3.086) 178(26.758,-3.086) 179(27.258,3.086) 180(27.258,-3.086)
  rect 2.54x0.635 smd: 181(-28.452,0) 184(-11.561,0) 185(-8.449,0) 188(8.442,0) 189(11.553,0) 192(28.444,0)
  rect 4.699x0.635 smd: 182(-23.181,0) 183(-16.831,0) 186(-3.179,0) 187(3.171,0) 190(16.824,0) 191(23.174,0)
unnamed#2
  round 1.016 smd: (0,0)

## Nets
GND: J1.5 J1.6 J1.11 J1.12 J1.17 J1.18 J1.23 J1.24 J1.29 J1.30 J1.35 J1.36 J1.41 J1.42 J1.47 J1.48 J1.53 J1.54 J1.59 J1.60 J1.61 J1.62 J1.67 J1.68 J1.73 J1.74 J1.79 J1.80 J1.85 J1.86 J1.91 J1.92 J1.97 J1.98 J1.103 J1.104 J1.110 J1.116 J1.121(GND#121) J1.122(GND#122) J1.123(GND#123) J1.124(GND#124) J1.125(GND#125) J1.126(GND#126) J1.127(GND#127) J1.128(GND#128) J2.8 J2.9 J2.10 J2.65 J2.66 J2.71 J2.72 J2.77 J2.78 J2.83 J2.84 J2.89 J2.90 J2.95 J2.96 J2.101 J2.102 J2.107 J2.108 J2.113 J2.114 J2.119 J2.120 J2.125 J2.126 J2.131 J2.132 J2.137 J2.138 J2.143 J2.144 J2.149 J2.150 J2.155 J2.156 J2.161 J2.162 J2.167 J2.168 J2.173 J2.174 J2.179 J2.180 J2.181(GND#181) J2.182(GND#182) J2.183(GND#183) J2.184(GND#184) J2.185(GND#185) J2.186(GND#186) J2.187(GND#187) J2.188(GND#188) J2.189(GND#189) J2.190(GND#190) J2.191(GND#191) J2.192(GND#192) J3.A1 J3.A4 J3.A5 J3.A8 J3.A9 J3.A12 J3.A13 J3.A16 J3.A17 J3.A20 J3.A21 J3.A24 J3.A25 J3.A28 J3.A29 J3.A32 J3.A33 J3.A36 J3.A37 J3.A40 J3.B2 J3.B3 J3.B6 J3.B7 J3.B10 J3.B11 J3.B14 J3.B15 J3.B18 J3.B19 J3.B22 J3.B23 J3.B26 J3.B27 J3.B30 J3.B31 J3.B34 J3.B35 J3.B38 J3.B39 J3.C1 J3.C4 J3.C5 J3.C8 J3.C9 J3.C12 J3.C13 J3.C16 J3.C17 J3.C20 J3.C21 J3.C24 J3.C25 J3.C28 J3.C29 J3.C32 J3.C33 J3.C36 J3.C38 J3.C40 J3.D2 J3.D3 J3.D6 J3.D7 J3.D10 J3.D13 J3.D16 J3.D19 J3.D22 J3.D25 J3.D28 J3.D37 J3.D39 J3.E1 J3.E4 J3.E5 J3.E8 J3.E11 J3.E14 J3.E17 J3.E20 J3.E23 J3.E26 J3.E29 J3.E32 J3.E35 J3.E38 J3.E40 J3.F2 J3.F3 J3.F6 J3.F9 J3.F12 J3.F15 J3.F18 J3.F21 J3.F24 J3.F27 J3.F30 J3.F33 J3.F36 J3.F39 J3.G1 J3.G4 J3.G5 J3.G8 J3.G11 J3.G14 J3.G17 J3.G20 J3.G23 J3.G26 J3.G29 J3.G32 J3.G35 J3.G38 J3.G40 J3.H3 J3.H6 J3.H9 J3.H12 J3.H15 J3.H18 J3.H21 J3.H24 J3.H27 J3.H30 J3.H33 J3.H36 J3.H39 J3.J1 J3.J4 J3.J5 J3.J8 J3.J11 J3.J14 J3.J17 J3.J20 J3.J23 J3.J26 J3.J29 J3.J32 J3.J35 J3.J38 J3.J40 J3.K2 J3.K3 J3.K6 J3.K9 J3.K12 J3.K15 J3.K18 J3.K21 J3.K24 J3.K27 J3.K30 J3.K33 J3.K36 J3.K39 J4.181(GND#181) J4.182(GND#182) J4.183(GND#183) J4.184(GND#184) J4.185(GND#185) J4.186(GND#186) J4.187(GND#187) J4.188(GND#188) J4.189(GND#189) J4.190(GND#190) J4.191(GND#191) J4.192(GND#192)
ADC_A0N: J1.96 J3.K26
ADC_A0P: J1.94 J3.K25
ADC_A1N: J1.90 J3.J25
ADC_A1P: J1.88 J3.J24
ADC_A2N: J1.84 J3.F23
ADC_A2P: J1.82 J3.F22
ADC_A3N: J1.78 J3.E22
ADC_A3P: J1.76 J3.E21
ADC_A4N: J1.72 J3.D9
ADC_A4P: J1.70 J3.D8
ADC_A5N: J1.66 J3.G10
ADC_A5P: J1.64 J3.G9
ADC_A6N: J1.52 J3.H8
ADC_A6P: J1.50 J3.H7
ADC_A7N: J1.46 J3.K8
ADC_A7P: J1.44 J3.K7
ADC_A8N: J1.40 J3.J7
ADC_A8P: J1.38 J3.J6
ADC_A9N: J1.34 J3.G7
ADC_A9P: J1.32 J3.G6
ADC_A10N: J1.28 J3.F5
ADC_A10P: J1.26 J3.F4
ADC_A11N: J1.22 J3.E3
ADC_A11P: J1.20 J3.E2
ADC_B0N: J1.21 J3.F26
ADC_B0P: J1.19 J3.F25
ADC_B1N: J1.27 J3.E28
ADC_B1P: J1.25 J3.E27
ADC_B2N: J1.33 J3.J28
ADC_B2P: J1.31 J3.J27
ADC_B3N: J1.39 J3.K29
ADC_B3P: J1.37 J3.K28
ADC_B4N: J1.45 J3.F29
ADC_B4P: J1.43 J3.F28
ADC_B5N: J1.51 J3.J31
ADC_B5P: J1.49 J3.J30
ADC_B6N: J1.71 J3.K32
ADC_B6P: J1.69 J3.K31
ADC_B7N: J1.77 J3.E25
ADC_B7P: J1.75 J3.E24
ADC_B8N: J1.83 J4.88
ADC_B8P: J1.81 J4.86
ADC_B9N: J1.89 J4.82
ADC_B9P: J1.87 J4.80
ADC_B10N: J1.95 J4.76
ADC_B10P: J1.93 J4.74
ADC_B11N: J1.101 J4.70
ADC_B11P: J1.99 J4.68
CLKOUTAN: J1.58 J3.H5
CLKOUTAP: J1.56 J3.H4
CONN_G0: J1.109 J4.73
CONN_G1: J1.111 J4.75
CONN_G2: J1.113 J4.79
CONN_G3: J1.115 J4.81
CONN_G4: J1.117 J4.85
CONN_G5: J1.119 J4.87
CONN_LATA: J1.105 J4.67
CONN_LATB: J1.107 J4.69
DA0N: J2.165 J3.C10
DA0P: J2.163 J3.C11
DA1N: J2.159 J3.D11
DA1P: J2.157 J3.D12
DA2N: J2.153 J3.H10
DA2P: J2.151 J3.H11
DA3N: J2.147 J3.C14
DA3P: J2.145 J3.C15
DA4N: J2.141 J3.G12
DA4P: J2.139 J3.G13
DA5N: J2.135 J3.D14
DA5P: J2.133 J3.D15
DA6N: J2.129 J3.G15
DA6P: J2.127 J3.G16
DA7N: J2.123 J3.J15
DA7P: J2.121 J3.J16
DA8N: J2.111 J3.D17
DA8P: J2.109 J3.D18
DA9N: J2.105 J3.G18
DA9P: J2.103 J3.G19
DA10N: J2.99 J3.J18
DA10P: J2.97 J3.J19
DA11N: J2.93 J3.K19
DA11P: J2.91 J3.K20
DA12N: J2.87 J3.E18
DA12P: J2.85 J3.E19
DA13N: J2.81 J3.D20
DA13P: J2.79 J3.D21
DA14N: J2.75 J3.H22
DA14P: J2.73 J3.H23
DA15N: J2.69 J3.C22
DA15P: J2.67 J3.C23
DAC_RST: J4.139 R5.1
DATACLKN: J2.115 J3.J10
DATACLKP: J2.117 J3.J9
DB0N: J2.166 J3.F7
DB0P: J2.164 J3.F8
DB1N: J2.160 J3.E9
DB1P: J2.158 J3.E10
DB2N: J2.154 J3.E12
DB2P: J2.152 J3.E13
DB3N: J2.148 J3.J12
DB3P: J2.146 J3.J13
DB4N: J2.142 J3.F13
DB4P: J2.140 J3.F14
DB5N: J2.136 J3.E15
DB5P: J2.134 J3.E16
DB6N: J2.130 J3.F16
DB6P: J2.128 J3.F17
DB7N: J2.124 J3.J21
DB7P: J2.122 J3.J22
DB8N: J2.112 J3.K22
DB8P: J2.110 J3.K23
DB9N: J2.106 J3.G24
DB9P: J2.104 J3.G25
DB10N: J2.100 J3.H25
DB10P: J2.98 J3.H26
DB11N: J2.94 J3.C26
DB11P: J2.92 J3.C27
DB12N: J2.88 J3.H31
DB12P: J2.86 J3.H32
DB13N: J2.82 J3.H34
DB13P: J2.80 J3.H35
DB14N: J2.76 J3.G36
DB14P: J2.74 J3.G37
DB15N: J2.70 J3.H37
DB15P: J2.68 J3.H38
FPGA_CLKOUTN1: J2.118 J3.G3
FPGA_CLKOUTN2: J2.33 J3.K5
FPGA_CLKOUTP1: J2.116 J3.G2
FPGA_CLKOUTP2: J2.31 J3.K4
GPIO_0: J4.127 R8.2
GPIO_1: J4.129 R12.2
GPIO_2: J4.133 R14.2
ISTROBE_N: J2.178 J3.H13
ISTROBE_P: J2.176 J3.H14
OVR_AN: J1.16 J4.100
OVR_AP: J1.14 J4.98
OVR_BN: J1.10 J4.94
OVR_BP: J1.8 J4.92
PARITY_N: J2.172 J3.F10
PARITY_P: J2.170 J3.F11
PRESENT: J2.21 J4.145
SYNCA_N: J2.177 J3.E6
SYNCA_P: J2.175 J3.E7
TXEN: J2.27 J4.135
TXSP1: J4.103 R1.1
TXSP2: J4.105 R2.1
TXSP3: J4.109 R3.1
TXSP4: J4.111 R4.1
TXSP5: J4.121 R7.1
TXSP6: J4.123 R9.1
N18163859: J2.49 R8.1
N18163866: J2.55 R12.1
N18163868: J2.57 R14.1
N18164112: J2.38 R3.2
N18164130: J2.40 R4.2
N18164140: J2.50 R7.2
N18164142: J2.52 R9.2
N18166476: J2.48 R5.2
N18166670: J2.26 R1.2
N18166673: J2.28 R2.2
N18255028: J3.G28
N18255030: J3.G21
N18255032: J3.G27
N18255034: J3.G31
N18255036: J3.G30
N18255042: J3.G22

Pads without a net: J1 1 2 3 4 7 9 13 15 55 57 63 65 100 102 106 108 112 114 118 120; J2 1 2 3 4 5 6 7 11 12 13 14 15 16 17 18 19 20 22 23 24 25 29 30 32 34 35 36 37 39 41 42 43 44 45 46 47 51 53 54 56 58 59 60 61 62 63 64 169 171; J3 A2 A3 A6 A7 A10 A11 A14 A15 A18 A19 A22 A23 A26 A27 A30 A31 A34 A35 A38 A39 B1 B4 B5 B8 B9 B12 B13 B16 B17 B20 B21 B24 B25 B28 B29 B32 B33 B36 B37 B40 C2 C3 C6 C7 C18 C19 C30 C31 C34 C35 C37 C39 D1 D4 D5 D23 D24 D26 D27 D29 D30 D31 D32 D33 D34 D35 D36 D38 D40 E30 E31 E33 E34 E36 E37 E39 F1 F19 F20 F31 F32 F34 F35 F37 F38 F40 G33 G34 G39 H1 H2 H16 H17 H19 H20 H28 H29 H40 J2 J3 J33 J34 J36 J37 J39 K1 K10 K11 K13 K14 K16 K17 K34 K35 K37 K38 K40; J4 1 2 3 4 5 6 7 8 9 10 11 12 13 14 15 16 17 18 19 20 21 22 23 24 25 26 27 28 29 30 31 32 33 34 35 36 37 38 39 40 41 42 43 44 45 46 47 48 49 50 51 52 53 54 55 56 57 58 59 60 61 62 63 64 65 66 71 72 77 78 83 84 89 90 91 93 95 96 97 99 101 102 104 106 107 108 110 112 113 114 115 116 117 118 119 120 122 124 125 126 128 130 131 132 134 136 137 138 140 141 142 143 144 146 147 148 149 150 151 152 153 154 155 156 157 158 159 160 161 162 163 164 165 166 167 168 169 170 171 172 173 174 175 176 177 178 179 180

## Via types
v1: diameter 0.508, hole 0.254, TOP to BOTTOM, 1272 vias

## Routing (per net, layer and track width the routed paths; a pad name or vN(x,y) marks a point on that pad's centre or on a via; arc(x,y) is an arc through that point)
GND: length 280.2
  TOP w0.165: 226.69,45.78 v1(226.69,45.8)
  TOP w0.254: J2.89 v1(222.05,57.97) ; J2.108 v1(231.08,53.46) ; J2.144 v1(231.08,39.46) ; J2.77 v1(222.05,60.97) ; J2.84 v1(231.08,59.47) ; J2.173 v1(222.05,31.96) ; J2.167 v1(222.05,33.46) ; J2.107 v1(222.05,53.46) ; J2.8 v1(228.04,83.47) ; J2.161 v1(222.05,34.96) ; J2.162 v1(231.08,34.96) ; J2.143 v1(222.05,39.46) ; J2.96 v1(231.08,56.46) ; J2.72 v1(231.08,62.47) ; J2.150 v1(231.08,37.96) ; J2.78 v1(231.08,60.97) ; J2.149 v1(222.05,37.96) ; J2.155 v1(222.05,36.46) ; J2.174 v1(231.08,31.96) ; J2.138 v1(231.08,40.97) ; J2.113 v1(225.35,51.96) ; J2.156 v1(231.08,36.46) ; J2.102 v1(231.08,54.96) ; J2.95 v1(222.05,56.46) ; J2.114 v1(231.08,51.96) ; J2.66 v1(231.08,63.97) ; J2.125 v1(222.05,43.97) ; J2.126 v1(231.08,43.97) ; J2.168 v1(231.08,33.46) ; J2.179 v1(222.05,30.46) ; J2.10 v1(231.08,82.97) ; J2.9 v1(225.35,82.97) ; J2.83 v1(222.05,59.47) ; J2.120 v1(231.08,50.46) ; J2.119 v1(225.35,50.46) ; J2.137 v1(222.05,40.97) ; J2.71 v1(222.05,62.47) ; J2.180 v1(231.08,30.46) ; J2.65 v1(222.05,63.97) ; J2.132 v1(231.08,42.47) ; J2.131 v1(222.05,42.47) ; J2.90 v1(231.08,57.97) ; J2.101 v1(222.05,54.96)
  BOTTOM w0.165: v1(204.54,144.31) 204.54,144.32 ; v1(203.03,138.39) 203.04,138.39 ; J1.103 v1(181.04,135.25) ; v1(204.54,138.39) 204.54,138.39 ; v1(212.09,139.71) J1.121 ; v1(197.11,139.71) v1(196.22,139.71) ; v1(206.04,144.31) 206.04,144.31 ; J1.123 v1(201.48,139.71) v1(203.07,139.71) ; 201.54,144.32 v1(201.53,144.31) ; v1(198.53,138.39) 198.54,138.38 ; J1.116 178.03,142.59 ; 198.54,144.32 v1(198.53,144.31) ; v1(209.04,138.39) 209.04,138.39 ; v1(200.03,138.39) 200.04,138.38 ; v1(207.54,138.39) 207.54,138.39 ; 200.04,144.32 v1(200.03,144.31) ; v1(191.54,138.39) 191.54,138.39 ; v1(201.53,138.39) 201.54,138.38 ; v1(209.17,139.71) v1(207.77,139.71) J1.122 v1(205.99,139.71) ; v1(197.03,138.39) 197.04,138.38 ; J1.110 179.53,142.59 ; 197.04,144.32 v1(197.03,144.31) ; v1(185.53,138.39) 185.54,138.38 ; v1(182.53,138.39) 182.54,138.38 ; v1(206.04,138.39) 206.04,138.39 ; v1(184.03,138.39) 184.04,138.38 ; v1(203.03,144.31) 203.04,144.32 ; v1(188.54,138.39) 188.54,138.39 ; v1(187.04,138.39) 187.04,138.39 ; v1(190.04,138.39) 190.04,138.39
  BOTTOM w0.254: v1(210.54,138.39) 210.54,136.84 J1.5 ; 188.54,138.39 J1.73 ; v1(187.04,144.31) 187.04,142.59 J1.80 ; 187.04,138.39 J1.79 ; J1.60 197.04,144.32 ; 207.54,138.39 J1.17 ; 204.54,138.39 J1.29 ; 182.54,138.38 J1.97 ; J1.42 201.54,144.32 ; v1(188.54,144.31) 188.54,142.58 J1.74 ; J1.104 181.03,142.59 v1(181.03,144.31) ; v1(207.54,144.31) 207.54,142.58 J1.18 ; 185.54,138.38 J1.85 ; 179.53,142.59 v1(179.53,144.31) ; v1(184.03,144.31) 184.03,142.59 J1.92 ; v1(190.04,144.31) 190.04,142.58 J1.68 ; v1(182.53,144.31) 182.53,142.59 J1.98 ; v1(191.54,144.31) 191.54,142.58 J1.62 ; 198.54,138.38 J1.53 ; 209.04,138.39 J1.11 ; v1(185.53,144.31) 185.53,142.59 J1.86 ; 190.04,138.39 J1.67 ; J1.54 198.54,144.32 ; 206.04,144.31 J1.24 ; 206.04,138.39 J1.23 ; 178.03,142.59 v1(178.03,144.31) ; J1.48 200.04,144.32 ; 204.54,144.32 J1.30 ; 200.04,138.38 J1.47 ; 191.54,138.39 J1.61 ; J1.12 209.04,142.58 v1(209.04,144.31) ; J1.6 210.54,142.58 v1(210.54,144.31) ; 201.54,138.38 J1.41 ; 184.04,138.38 J1.91 ; 203.04,138.39 J1.35 ; 203.04,144.32 J1.36 ; 197.04,138.38 J1.59
  BOTTOM w0.508: v1(99.07,60.36) J3.C40 ; v1(104.15,42.58) J3.G26 ; v1(104.15,46.39) J3.G29 ; v1(99.07,29.88) J3.C16 ; v1(106.69,46.39) J3.J29 ; v1(106.69,27.34) J3.J14 ; v1(104.15,50.2) J3.G32 ; v1(97.8,17.18) J3.B6 ; v1(96.53,31.15) J3.A17 ; v1(107.96,13.37) J3.K3 ; v1(99.07,36.23) J3.C21 ; v1(105.42,59.09) J3.H39 ; v1(96.53,45.12) J3.A28 ; v1(105.42,17.18) J3.H6 ; v1(101.61,46.39) J3.E29 ; v1(96.53,46.39) J3.A29 ; v1(107.96,47.66) J3.K30 ; v1(105.42,40.04) J3.H24 ; v1(96.53,10.83) J3.A1 ; v1(101.61,31.15) J3.E17 ; v1(97.8,54.01) J3.B35 ; v1(97.8,57.82) J3.B38 ; v1(100.34,12.1) J3.D2 ; v1(96.53,60.36) J3.A40 ; v1(97.8,48.93) J3.B31 ; v1(105.42,24.8) J3.H12 ; v1(102.88,20.99) J3.F9 ; J3.K9 v1(106.69,19.72) J3.J8 ; v1(102.88,32.42) J3.F18 ; v1(106.69,50.2) J3.J32 ; v1(106.69,54.01) J3.J35 ; v1(100.34,17.18) J3.D6 ; v1(107.96,28.61) J3.K15 ; v1(100.34,37.5) J3.D22 ; v1(107.96,59.09) J3.K39 ; v1(104.15,31.15) J3.G17 ; v1(100.34,45.12) J3.D28 ; v1(105.42,28.61) J3.H15 ; v1(106.69,42.58) J3.J26 ; v1(99.07,19.72) J3.C8 ; v1(102.88,17.18) J3.F6 ; v1(106.69,34.96) J3.J20 ; v1(97.8,43.85) J3.B27 ; 101.61,42.58 J3.E26 ; v1(104.15,15.91) J3.G5 ; v1(96.53,14.64) J3.A4 ; v1(102.88,36.23) J3.F21 ; v1(96.53,51.47) J3.A33 ; v1(102.88,13.37) J3.F3 ; v1(99.07,14.64) J3.C4 ; v1(99.07,34.96) J3.C20 ; v1(104.15,60.36) J3.G40 ; v1(107.96,36.23) J3.K21 ; v1(97.8,23.53) J3.B11 ; v1(105.42,20.99) J3.H9 ; v1(104.15,38.77) J3.G23 ; v1(102.88,47.66) J3.F30 ; v1(107.96,24.8) J3.K12 ; v1(97.8,32.42) J3.B18 ; v1(105.42,51.47) J3.H33 ; v1(101.61,54.01) J3.E35 ; v1(101.61,60.36) J3.E40 ; v1(106.69,57.82) J3.J38 ; v1(99.07,15.91) J3.C5 ; v1(105.42,55.28) J3.H36 ; v1(97.8,52.74) J3.B34 ; v1(100.34,18.45) J3.D7 ; v1(99.07,50.2) J3.C32 ; v1(106.69,23.53) J3.J11 ; v1(101.61,14.64) J3.E4 ; v1(106.69,14.64) J3.J4 ; v1(104.15,14.64) J3.G4 ; v1(99.07,26.07) J3.C13 ; v1(99.07,57.82) J3.C38 ; v1(105.42,32.42) J3.H18 ; v1(105.42,36.23) J3.H21 ; v1(102.88,28.61) J3.F15 ; v1(99.07,46.39) J3.C29 ; v1(96.53,41.31) J3.A25 ; v1(96.53,50.2) J3.A32 ; v1(96.53,20.99) J3.A9 ; v1(96.53,40.04) J3.A24 ; v1(97.8,42.58) J3.B26 ; v1(101.61,34.96) J3.E20 ; v1(106.69,10.83) J3.J1 ; v1(96.53,56.55) J3.A37 ; v1(97.8,59.09) J3.B39 ; v1(107.96,17.18) J3.K6 ; v1(96.53,29.88) J3.A16 ; v1(105.42,13.37) J3.H3 ; v1(96.53,15.91) J3.A5 ; v1(106.69,60.36) J3.J40 ; v1(96.53,55.28) J3.A36 ; v1(99.07,55.28) J3.C36 ; v1(99.07,51.47) J3.C33 ; v1(100.34,29.88) J3.D16 ; v1(97.8,38.77) J3.B23 ; v1(101.61,19.72) J3.E8 ; v1(101.61,27.34) J3.E14 ; v1(104.15,19.72) J3.G8 ; v1(97.8,28.61) J3.B15 ; v1(99.07,40.04) J3.C24 ; v1(99.07,31.15) J3.C17 ; v1(107.96,12.1) J3.K2 ; v1(104.15,54.01) J3.G35 ; v1(104.15,34.96) J3.G20 ; v1(107.96,51.47) J3.K33 ; v1(99.07,10.83) J3.C1 ; v1(106.69,31.15) J3.J17 ; v1(107.96,43.85) J3.K27 ; v1(104.15,57.82) J3.G38 ; v1(100.34,13.37) J3.D3 ; v1(102.88,43.85) J3.F27 ; v1(106.69,15.91) J3.J5 ; v1(100.34,56.55) J3.D37 ; v1(100.34,22.26) J3.D10 ; v1(101.61,57.82) J3.E38 ; v1(96.53,24.8) J3.A12 ; v1(100.34,41.31) J3.D25 ; v1(102.88,55.28) J3.F36 ; v1(97.8,13.37) J3.B3 ; v1(107.96,55.28) J3.K36 ; v1(102.88,12.1) J3.F2 ; v1(97.8,47.66) J3.B30 ; v1(104.15,10.83) J3.G1 ; v1(100.34,33.69) J3.D19 ; v1(100.34,59.09) J3.D39 ; v1(97.8,22.26) J3.B10 ; v1(97.8,37.5) J3.B22 ; v1(97.8,27.34) J3.B14 ; v1(97.8,33.69) J3.B19 ; v1(107.96,32.42) J3.K18 ; v1(99.07,45.12) J3.C28 ; v1(104.15,27.34) J3.G14 ; v1(99.07,20.99) J3.C9 ; v1(101.61,15.91) J3.E5 ; v1(101.61,23.53) J3.E11 ; v1(101.61,38.77) J3.E23 ; v1(96.53,36.23) J3.A21 ; v1(102.88,59.09) J3.F39 ; v1(96.53,26.07) J3.A13 ; v1(99.07,41.31) J3.C25 ; v1(97.8,12.1) J3.B2 ; v1(100.34,26.07) J3.D13 ; v1(102.88,24.8) J3.F12 ; v1(101.61,10.83) J3.E1 ; v1(105.42,43.85) J3.H27 ; v1(96.53,19.72) J3.A8
  BOTTOM w0.635: v1(99.07,24.8) J3.C12 ; v1(96.53,34.96) J3.A20 ; v1(102.88,40.04) J3.F24 ; v1(107.96,40.04) J3.K24 ; v1(106.69,38.77) J3.J23 ; v1(104.15,23.53) J3.G11 ; v1(97.8,18.45) J3.B7 ; v1(105.42,47.66) J3.H30
  vias: v1(2.03,89.2) v1(2.14,115.33) v1(2.27,127.01) v1(2.79,98.81) v1(3.54,108.6) v1(4.32,92.9) v1(4.55,121.3) v1(5.82,132.22) v1(5.95,144.28) v1(6.1,92.9) v1(7.22,115.33) v1(7.35,127.01) v1(8.32,92.9) v1(8.62,108.6) v1(9.63,121.3) v1(10.48,92.9) v1(10.9,132.22) v1(11.03,144.28) v1(12.3,115.33) v1(12.43,127.01) v1(12.55,139.08) v1(12.64,92.9) v1(13.7,108.6) v1(13.97,102.23) v1(14.71,121.3) v1(14.67,92.9) v1(15.98,132.22) v1(16.11,144.28) v1(16.83,92.9) v1(17.27,115.32) v1(17.51,127.01) v1(17.63,139.08) v1(18.54,101.22) v1(18.8,108.46) v1(18.99,92.9) v1(19.43,102.87) v1(19.56,99.69) v1(21.19,144.28) v1(21.21,92.9) v1(22.59,127.01) v1(22.71,139.08) v1(22.99,92.9) v1(24.13,121.41) v1(24.32,92.9) v1(26.1,92.9) v1(26.27,144.28) v1(27.18,97.92) v1(27.79,139.08) v1(28.32,92.9) v1(29.59,126.49) v1(29.97,116.08) v1(29.97,106.3) v1(29.97,101.85) v1(30.48,92.9) v1(31.35,144.28) v1(31.62,104.14) v1(31.75,99.69) v1(32.64,92.9) v1(32.87,139.08) v1(33.27,105.79) v1(33.65,99.69) v1(33.78,115.32) v1(33.91,132.46) v1(34.67,99.69) v1(34.67,92.9) v1(35.05,114.05) v1(35.05,106.3) v1(35.81,121.92) v1(36.43,144.28) v1(36.83,92.9) v1(38.23,103.38) v1(38.35,100.84) v1(38.35,97.79) v1(38.59,120.41) v1(38.99,99.69) v1(38.99,92.9) v1(39.75,121.54) v1(40.26,103) v1(40.64,119.63) v1(40.89,126.87) v1(41.21,92.9) v1(42.99,92.9) v1(43.29,139.2) v1(44.33,92.9) v1(44.45,98.68) v1(44.56,129.3) v1(44.96,108.2) v1(45.21,126.87) v1(45.32,144.54) v1(45.97,101.35) v1(46.1,97.54) v1(46.1,92.9) v1(47.35,134) v1(47.62,125.86) v1(47.62,99.31) v1(48.37,139.2) v1(48.33,92.9) v1(48.75,120.41) v1(49.64,129.3) v1(50.4,144.54) v1(50.42,100.71) v1(50.42,97.79) v1(50.49,92.9) v1(52.07,125.98) v1(52.43,134) v1(52.7,116.71) v1(52.7,100.97) v1(52.7,97.66) v1(52.64,92.9) v1(53.45,139.2) v1(53.83,120.41) v1(53.97,91.19) v1(54.36,98.93) v1(54.72,129.3) v1(54.68,92.9) v1(55.48,144.54) v1(56.84,92.9) v1(57.51,134) v1(57.66,102.36) v1(58.53,139.2) v1(58.91,120.41) v1(58.99,92.9) v1(59.8,129.3) v1(60.56,144.54) v1(61.22,92.9) v1(62.1,98.93) v1(62.59,134) v1(62.86,117.86) v1(62.99,92.9) v1(63.61,139.2) v1(63.99,120.41) v1(64.13,108.2) v1(64.88,129.3) v1(65.64,144.54) v1(65.64,123.33) v1(67.04,125.74) v1(67.67,134) v1(67.94,89.48) v1(68.05,104.18) v1(68.69,139.2) v1(69.07,120.41) v1(69.09,118.11) v1(69.96,129.3) v1(70.72,144.54) v1(70.72,123.33) v1(72.12,125.74) v1(72.24,106.18) v1(72.75,134) v1(73.77,139.2) v1(74.15,120.41) v1(75.04,129.3) v1(75.18,109.35) v1(75.8,144.54) v1(75.8,123.33) v1(77.2,125.74) v1(77.32,106.18) v1(77.83,134) v1(78.85,139.2) v1(79.12,117.98) v1(79.23,120.41) v1(80.12,129.3) v1(80.88,144.54) v1(80.88,123.33) v1(82.28,125.74) v1(82.4,106.18) v1(82.91,134) v1(83.93,139.2) v1(84.31,120.41) v1(85.09,109.47) v1(85.2,129.3) v1(85.96,144.54) v1(85.96,123.33) v1(87.36,125.74) v1(87.48,106.18) v1(87.99,134) v1(89.01,139.2) v1(89.15,117.98) v1(89.39,120.41) v1(90.28,129.3) v1(91.04,144.54) v1(91.04,123.33) v1(92.44,125.74) v1(92.56,106.18) v1(93.07,134) v1(94.09,139.2) v1(94.47,120.41) v1(95.12,109.35) v1(95.36,129.3) v1(96.12,144.54) v1(96.12,123.33) v1(96.99,67.7) v1(96.99,62.62) v1(97.09,7.58) v1(97.09,2.5) v1(97.52,125.74) v1(97.64,106.18) v1(98.15,134) v1(99.17,139.2) v1(99.67,120.41) v1(100.44,129.3) v1(101.2,144.54) v1(101.2,123.33) v1(101.6,118.11) v1(102.6,125.74) v1(102.72,106.18) v1(103.23,134) v1(104.39,109.6) v1(104.75,120.41) v1(105.64,139.08) v1(106.28,123.33) v1(107.04,129.3) v1(107.68,125.74) v1(107.8,106.18) v1(108.69,144.41) v1(109.23,67.98) v1(109.23,62.9) v1(109.23,57.82) v1(109.23,56.55) v1(109.23,55.28) v1(109.23,54.01) v1(109.23,52.74) v1(109.23,51.47) v1(109.23,50.2) v1(109.23,48.93) v1(109.23,46.39) v1(109.23,45.12) v1(109.23,43.85) v1(109.23,42.58) v1(109.23,41.31) v1(109.23,40.04) v1(109.23,38.77) v1(109.23,37.5) v1(109.23,36.23) v1(109.23,34.96) v1(109.23,33.69) v1(109.23,32.42) v1(109.23,31.15) v1(109.23,29.88) v1(109.23,28.61) v1(109.23,27.34) v1(109.23,26.07) v1(109.23,24.8) v1(109.23,23.53) v1(109.23,22.26) v1(109.23,19.72) v1(109.23,18.45) v1(109.23,17.18) v1(109.23,7.02) v1(109.23,1.94) v1(109.83,120.41) v1(110.72,139.08) v1(111.36,123.33) v1(111.51,117.98) v1(111.99,134) v1(112.12,129.3) v1(112.76,125.74) v1(112.88,106.18) v1(113.77,144.41) v1(114.31,67.98) v1(114.31,62.9) v1(114.31,10.07) v1(114.31,1.94) v1(114.91,120.41) v1(115.44,109.35) v1(115.8,139.08) v1(116.44,123.33) v1(117.07,134) v1(117.2,129.3) v1(117.84,125.74) v1(117.96,106.18) v1(118.85,144.41) v1(119.39,67.98) v1(119.39,62.9) v1(119.39,57.82) v1(119.39,56.55) v1(119.39,55.28) v1(119.39,51.47) v1(119.39,50.2) v1(119.39,43.85) v1(119.39,41.31) v1(119.39,40.04) v1(119.39,37.5) v1(119.39,36.23) v1(119.39,34.96) v1(119.39,33.69) v1(119.39,32.42) v1(119.39,31.15) v1(119.39,27.34) v1(119.39,26.07) v1(119.39,23.53) v1(119.39,1.94) v1(119.99,120.41) v1(120.88,139.08) v1(121.52,123.33) v1(122.15,134) v1(122.28,129.3) v1(122.92,125.74) v1(123.04,106.18) v1(123.82,117.98) v1(123.93,144.41) v1(123.95,22.99) v1(124.47,67.98) v1(124.47,62.9) v1(124.47,10.07) v1(124.47,1.94) v1(125.07,120.41) v1(125.73,109.47) v1(125.96,139.08) v1(127.23,134) v1(127.36,129.3) v1(127.51,59.31) v1(128.12,106.18) v1(129.01,144.41) v1(129.55,67.98) v1(129.55,51.47) v1(129.55,50.2) v1(129.55,46.39) v1(129.55,45.12) v1(129.55,43.85) v1(129.55,42.58) v1(129.55,41.31) v1(129.55,37.5) v1(129.55,36.23) v1(129.55,33.69) v1(129.55,32.42) v1(129.55,31.15) v1(129.55,29.88) v1(129.55,28.61) v1(129.55,27.34) v1(129.55,24.8) v1(129.55,22.26) v1(129.55,18.45) v1(129.55,7.02) v1(129.55,1.94) v1(130.15,120.41) v1(130.28,123.33) v1(131.04,139.08) v1(131.68,125.74) v1(132.31,134) v1(132.44,129.3) v1(132.46,64.52) v1(133.32,96.04) v1(133.32,88.42) v1(133.32,80.8) v1(133.32,73.18) v1(133.45,106.05) v1(134.09,144.41) v1(134.49,118.11) v1(134.49,51.56) v1(134.63,10.07) v1(134.63,1.94) v1(135.23,120.41) v1(135.36,123.33) v1(135.38,47.24) v1(136.12,139.08) v1(136.65,58.04) v1(136.76,125.74) v1(137.03,109.22) v1(137.39,134) v1(137.52,129.3) v1(138.43,70.36) v1(139.17,144.41) v1(139.71,56.55) v1(139.71,51.47) v1(139.71,46.39) v1(139.71,42.58) v1(139.71,41.31) v1(139.71,40.04) v1(139.71,38.77) v1(139.71,37.5) v1(139.71,34.96) v1(139.71,32.42) v1(139.71,31.15) v1(139.71,29.88) v1(139.71,28.61) v1(139.71,18.45) v1(139.71,7.02) v1(139.71,1.94) v1(139.83,106.05) v1(140.31,120.41) v1(140.33,94.11) v1(140.44,123.33) v1(141.2,139.08) v1(141.22,84.71) v1(141.84,125.74) v1(142.47,134) v1(142.6,129.3) v1(142.62,76.71) v1(142.75,44.83) v1(143.51,64.52) v1(143.51,23.24) v1(144.25,144.41) v1(144.79,10.07) v1(144.79,1.94) v1(145.39,120.41) v1(145.52,123.33) v1(146.28,139.08) v1(146.3,59.05) v1(146.92,125.74) v1(147.45,64.39) v1(147.55,134) v1(147.57,99.57) v1(147.57,89.66) v1(147.68,129.3) v1(147.95,80.14) v1(148.34,109.6) v1(149.1,50.8) v1(149.33,144.41) v1(149.86,117.47) v1(149.87,42.58) v1(149.87,41.31) v1(149.87,40.04) v1(149.87,38.77) v1(149.87,34.96) v1(149.87,33.69) v1(149.87,29.88) v1(149.87,28.61) v1(149.87,18.45) v1(149.87,7.02) v1(149.87,1.94) v1(150.47,120.41) v1(150.6,123.33) v1(151,89.92) v1(151.13,79.12) v1(151.36,139.08) v1(151.89,64.01) v1(151.89,23.37) v1(152,125.74) v1(152.02,96.9) v1(152.15,69.22) v1(152.27,76.96) v1(152.63,134) v1(152.76,129.3) v1(152.91,74.55) v1(154.05,55.88) v1(154.41,144.41) v1(154.94,100.46) v1(154.95,10.07) v1(154.95,1.94) v1(155.55,120.41) v1(156.44,139.08) v1(156.59,45.85) v1(156.97,64.9) v1(157.23,74.04) v1(157.71,134) v1(157.73,42.55) v1(157.84,129.3) v1(158.5,71.25) v1(159.49,144.41) v1(159.64,49.66) v1(160.03,57.82) v1(160.03,40.04) v1(160.03,38.77) v1(160.03,34.96) v1(160.03,32.42) v1(160.03,31.15) v1(160.03,29.88) v1(160.03,28.61) v1(160.03,27.34) v1(160.03,26.07) v1(160.03,23.53) v1(160.03,18.45) v1(160.03,7.02) v1(160.03,1.94) v1(160.91,68.58) v1(161.04,88.9) v1(161.16,85.47) v1(161.29,78.87) v1(161.52,139.08) v1(161.54,75.18) v1(162.05,54.48) v1(162.18,46.86) v1(162.31,99.82) v1(162.31,83.82) v1(162.69,41.91) v1(162.79,134) v1(162.81,65.15) v1(162.92,129.3) v1(164.46,53.34) v1(164.57,144.41) v1(164.72,44.58) v1(165.11,10.07) v1(165.11,1.94) v1(165.86,56.52) v1(165.99,78.23) v1(166.24,100.33) v1(166.37,68.71) v1(166.88,104.65) v1(167,94.74) v1(167.13,91.44) v1(167.26,65.41) v1(167.26,42.55) v1(167.87,134) v1(168.02,76.2) v1(168.15,57.91) v1(169.42,83.06) v1(169.54,60.96) v1(170.19,50.2) v1(170.19,48.93) v1(170.19,45.12) v1(170.19,36.23) v1(170.19,34.96) v1(170.19,33.69) v1(170.19,32.42) v1(170.19,31.15) v1(170.19,29.88) v1(170.19,28.61) v1(170.19,27.34) v1(170.19,26.07) v1(170.19,23.53) v1(170.19,18.45) v1(170.19,10.07) v1(170.19,7.02) v1(170.19,1.94) v1(171.2,41.27) v1(171.58,74.68) v1(172.59,85.22) v1(172.97,80.77) v1(173.99,49.15) v1(175.21,139.71) v1(175.26,65.41) v1(175.27,7.02) v1(175.27,1.94) v1(175.39,100.84) v1(176.22,139.71) v1(177.24,139.71) v1(177.42,40.13) v1(177.55,85.72) v1(177.67,68.45) v1(177.8,106.55) v1(177.8,90.55) v1(178.94,139.71) v1(180.35,46.39) v1(180.35,43.85) v1(180.35,29.88) v1(180.35,28.61) v1(180.35,26.07) v1(180.35,23.53) v1(180.35,18.45) v1(180.35,10.07) v1(180.35,1.94) v1(180.47,80.01) v1(180.72,103.76) v1(181.36,65.41) v1(181.48,139.71) v1(182.25,90.42) v1(182.75,118.11) v1(182.88,74.04) v1(183.26,139.71) v1(183.39,48.51) v1(183.77,40.39) v1(183.9,100.58) v1(184.02,82.8) v1(184.53,115.06) v1(185.17,97.79) v1(185.17,69.98) v1(185.43,7.02) v1(185.43,1.94) v1(185.55,139.71) v1(185.55,35.43) v1(185.67,65.28) v1(185.8,111.38) v1(185.8,42.16) v1(186.06,56.39) v1(186.06,48.9) v1(186.44,94.36) v1(187.07,139.71) v1(187.96,28.07) v1(188.21,78.74) v1(188.47,139.71) v1(188.59,37.59) v1(189.1,46.61) v1(189.1,40.64) v1(189.87,65.28) v1(189.99,69.22) v1(190.12,93.34) v1(190.51,51.47) v1(190.51,23.53) v1(190.51,18.45) v1(190.5,13.84) v1(190.51,10.07) v1(190.51,1.94) v1(191.39,75.56) v1(191.46,139.71) v1(191.64,35.94) v1(191.77,40.77) v1(191.9,60.96) v1(192.28,49.15) v1(192.48,139.71) v1(193.17,83.06) v1(193.42,139.71) v1(193.76,145.3) v1(194.06,26.54) v1(194.56,79.25) v1(194.56,38.86) v1(194.56,35.05) v1(194.69,69.72) v1(195.07,46.99) v1(195.21,139.71) v1(195.45,74.8) v1(195.59,7.02) v1(195.59,1.94) v1(195.71,65.28) v1(196.98,86.36) v1(197.49,113.41) v1(197.61,39.12) v1(197.74,26.54) v1(198.25,100.33) v1(198.94,139.71) v1(199.52,83.44) v1(199.52,26.04) v1(200.41,107.06) v1(200.53,15.49) v1(200.66,75.95) v1(200.67,57.82) v1(200.67,56.55) v1(200.67,50.2) v1(200.67,43.85) v1(200.67,42.58) v1(200.67,37.5) v1(200.67,33.69) v1(200.67,23.53) v1(200.67,18.45) v1(200.66,13.84) v1(200.67,10.07) v1(200.67,1.94) v1(200.79,69.47) v1(201.04,96.52) v1(202.06,81.15) v1(202.69,64.52) v1(203.2,113.41) v1(203.96,100.08) v1(204.22,26.29) v1(204.6,79.5) v1(204.6,30.73) v1(205.1,35.81) v1(205.75,7.02) v1(205.75,1.94) v1(205.99,75.18) v1(206.25,60.96) v1(206.76,109.47) v1(206.76,97.28) v1(207.14,35.94) v1(207.14,30.48) v1(208.03,69.85) v1(209.68,120.78) v1(210.57,13.84) v1(210.69,10.16) v1(210.83,57.82) v1(210.83,56.55) v1(210.83,43.85) v1(210.83,42.58) v1(210.83,33.69) v1(210.83,28.61) v1(210.83,24.8) v1(210.83,18.45) v1(210.83,1.94) v1(210.95,15.49) v1(211.2,64.9) v1(211.89,69.05) v1(212.47,59.44) v1(213.42,139.71) v1(214.08,145.3) v1(214.08,124.98) v1(214.08,119.9) v1(214.43,130.01) v1(214.43,114.77) v1(214.43,109.69) v1(214.43,104.61) v1(214.43,99.53) v1(214.43,94.45) v1(214.43,89.37) v1(214.76,54.99) v1(215.26,64.9) v1(215.4,86.3) v1(215.91,7.02) v1(215.91,1.94) v1(219.16,145.3) v1(219.16,124.98) v1(219.16,119.9) v1(219.51,135.09) v1(219.51,130.01) v1(219.51,114.77) v1(219.51,109.69) v1(219.51,104.61) v1(219.51,99.53) v1(219.51,94.45) v1(219.51,89.37) v1(219.96,14.1) v1(220.14,72.31) v1(220.34,27.05) v1(220.34,21.21) v1(220.48,86.3) v1(220.6,64.9) v1(220.73,48.69) v1(220.73,46.46) v1(220.9,39.45) v1(220.98,10.16) v1(220.99,1.94) v1(221.11,42.42) v1(221.11,37.92) v1(221.18,40.92) v1(223.14,67.94) v1(223.39,19.3) v1(223.57,48.69) v1(224.24,145.3) v1(224.24,124.98) v1(224.24,119.9) v1(224.59,130.01) v1(224.59,114.77) v1(224.59,109.69) v1(224.59,104.61) v1(224.59,99.53) v1(226.07,17.18) v1(226.07,12.1) v1(226.07,1.94) v1(226.69,86.8) v1(226.69,84.77) v1(226.69,83.06) v1(226.69,80.9) v1(226.69,78.74) v1(226.69,76.71) v1(226.69,74.55) v1(226.69,72.39) v1(226.69,70.67) v1(226.69,68.64) v1(226.69,66.8) v1(226.69,64.77) v1(226.69,62.43) v1(226.69,60.89) v1(226.69,59.37) v1(226.69,56.46) v1(226.67,54.97) v1(226.69,52.38) v1(226.69,50.67) v1(226.69,48.64) v1(226.69,46.8) v1(226.69,42.44) v1(226.69,40.89) v1(226.69,39.57) v1(226.69,36.7) v1(226.69,34.54) v1(226.69,32.38) v1(226.69,30.67) v1(226.69,28.64) v1(229.32,145.3) v1(229.32,140.22) v1(229.32,124.98) v1(229.32,119.9) v1(229.67,135.09) v1(229.67,130.01) v1(229.67,114.77) v1(229.67,109.69) v1(229.67,104.61) v1(229.67,99.53) v1(230.64,86.3) v1(231.15,22.26) v1(231.15,17.18) v1(231.15,12.1) v1(231.15,7.02) v1(231.15,1.94) v1(231.47,28.02)
ADC_A0N: length 187.7
  LAYER6 w0.112: v1(107.96,42.58) 108.44,42.1 112.33,42.1 168.48,98.25 168.48,117.09 168.37,117.2 163.58,117.2 163.27,117.51 163.27,118.06 163.58,118.37 168.37,118.37 168.48,118.48 168.48,118.82 168.37,118.93 163.69,118.93 163.39,119.23 163.39,119.79 163.69,120.1 168.37,120.1 168.48,120.21 168.48,120.54 168.37,120.65 163.99,120.65 163.7,120.94 163.7,121.53 163.99,121.82 168.37,121.82 168.48,121.93 168.48,122.27 168.37,122.38 163.99,122.38 163.7,122.67 163.7,123.26 163.99,123.55 168.37,123.55 168.48,123.66 168.48,124 168.37,124.11 163.99,124.11 163.7,124.4 163.7,124.99 163.99,125.28 168.37,125.28 168.48,125.39 168.48,127.97 183.14,142.63 183.14,142.89 183.03,143 182.88,143 182.75,143.13 182.75,143.43 182.88,143.56 183.03,143.56 183.14,143.67 183.14,144.65 v1(182.84,144.95)
  BOTTOM w0.114: J1.96 183.04,143.9 183.14,144 183.14,144.65 v1(182.84,144.95) ; v1(107.96,42.58) J3.K26
